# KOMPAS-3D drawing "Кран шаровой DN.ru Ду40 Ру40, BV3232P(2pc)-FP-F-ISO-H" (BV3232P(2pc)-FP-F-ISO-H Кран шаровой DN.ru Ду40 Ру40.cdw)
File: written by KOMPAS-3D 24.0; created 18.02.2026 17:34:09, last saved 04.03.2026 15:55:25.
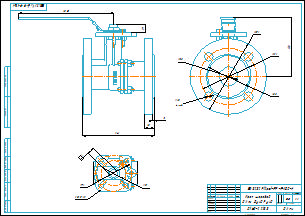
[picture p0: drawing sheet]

Document properties: Автор: R2D2; Форматы листов документа: A2; Полное имя файла: BV3232P(2pc)-FP-F-ISO-H Кран шаровой DN.ru Ду40 Ру40.m3d; Масса: 6.49; Наименование: Кран шаровой DN.ru Ду40 Ру40; Количество листов документа: 1; Примечание: D160-22133

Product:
- Part/product: Кран шаровой DN.ru Ду40 Ру40  | designation BV3232P(2pc)-FP-F-ISO-H
    Масса: 6.49
    Раздел спецификации: Прочие изделия
    Примечание: D160-22133

Views: Проекционный вид 2, Проекционный вид 3
Referenced files in E:\Работа\Зайцев\BV3232P(2pc)-FP-F-ISO-H Кран шаровой DN.ru Ду15-300 Ру16-40\DN40\: BV3232P(2pc)-FP-F-ISO-H Кран шаровой DN.ru Ду40 Ру40.m3d
Referenced files in E:\Работа\Зайцев\Для компаса\: чертеж DN.ru А3.cdt
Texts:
  BV3232P(2pc)-FP-F-ISO-H
  ISO 5211
  чертеж DN.ru А3.cdt
  Кран шаровой
  DN.ru Ду40 Ру40
  Кран шаровой DN.ru Ду40 Ру40
  BV3232P(2pc)-FP-F-ISO-H Кран шаровой DN.ru Ду40 Ру40
Dimensions and other numbers on the sheet: 0; 3; 4; 115; 150; 110; 88; 38; 18; 4 отв.; 70; 50; 14; 1:1; 1; 2; 6,49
